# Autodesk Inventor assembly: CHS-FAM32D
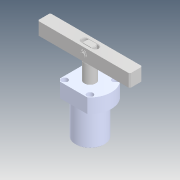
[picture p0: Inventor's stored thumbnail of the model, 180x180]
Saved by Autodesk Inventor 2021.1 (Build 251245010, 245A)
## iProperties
Created: 2020-02
Part Number: CHS-FAM32D
Description: STEP AP214
Document SubType Name: Assembly
Designer: user
Title: chs-fam32d_asm.STEP
Revision Number: ÈÎºÎ
Sending System: SolidWorks 2016
Preprocessor: SwSTEP 2.0
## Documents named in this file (6)
- D:\Vault_2016\Projekty\Clamptek\Hydraulic\CHS\CHS-32\Inventor\CHS-FAM32D\CHS-FAM32D.iam
- D:\Vault_2016\Projekty\Clamptek\Hydraulic\CHS\CHS-32\Inventor\CHS-FAM32D\CHS-32D-02_2.ipt
- D:\Vault_2016\Projekty\Clamptek\Hydraulic\CHS\CHS-32\Inventor\CHS-FAM32D\CHS-32D-01_3.ipt
- D:\Vault_2016\Projekty\Clamptek\Hydraulic\CHS\CHS-32\Inventor\CHS-FAM32D\CHS-FAM32BT.ipt
- D:\Vault_2016\Projekty\Clamptek\Hydraulic\CHS\CHS-32\Inventor\CHS-FAM32D\Xiaozhou_1.ipt
- D:\Vault_2016\Projekty\Clamptek\Hydraulic\CHS\CHS-32\Inventor\CHS-FAM32D\Öá8µ²È¦_1.ipt
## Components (6 placed, 6 different names)
1. CHS-32D-02_2_1
2. CHS-32D-01_3_2
3. CHS-FAM32BT_3
4. Xiaozhou_1_4
5. Öá8µ²È¦_1_5
6. Öá8µ²È¦_1_6
